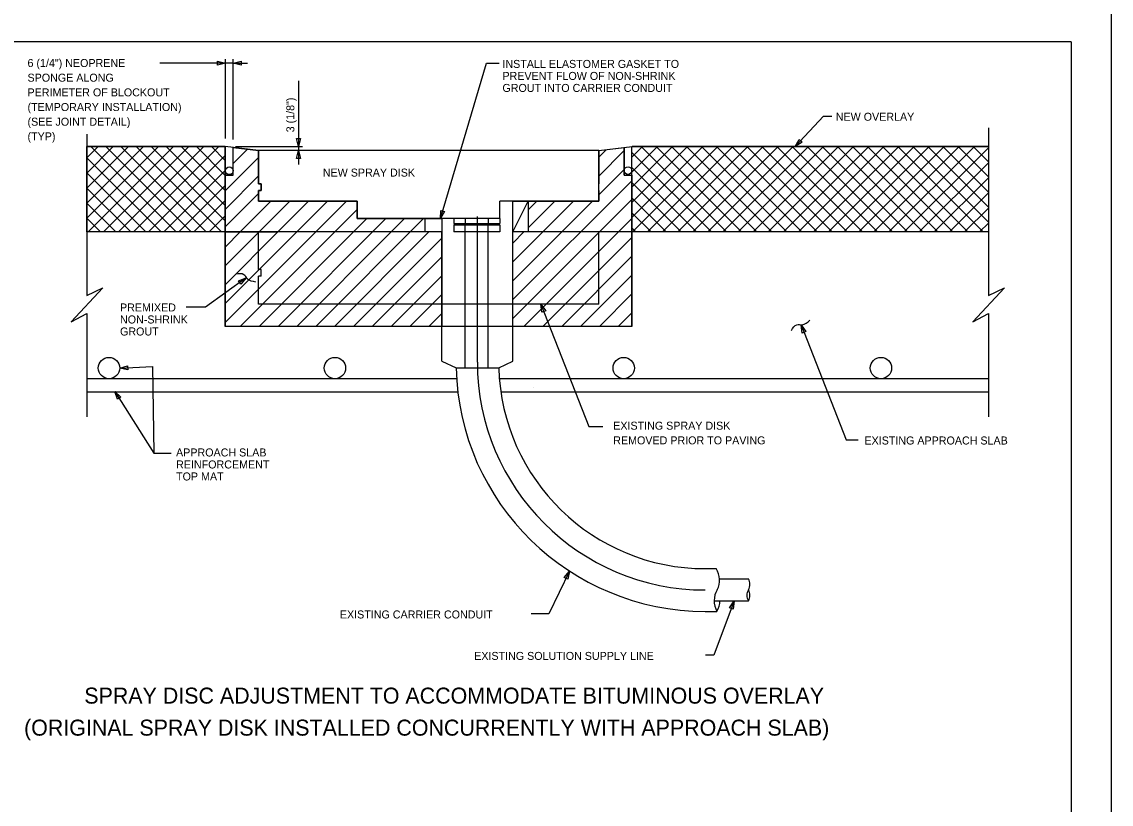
# Model space of a CAD drawing. Extents: x 3239 to 4230, y -4276 to -2494.
# Drawn here: x 3671.7 to 4080, y -3983 to -3689.8 of the extents above; entities that cross this region are included whole.
import ezdxf

# ---------------------------------------------------------------- set-up
doc = ezdxf.new("R2010")
doc.units = 0
doc.layers.add('2', color=7, linetype='Continuous')
doc.layers.add('PLT-BNDY', color=7, linetype='Continuous')

msp = doc.modelspace()

# ---------------------------------------------------------------- linework, layer by layer
at = {"layer": '2'}
for p, q in [((4065.03, -3697.29), (3279.03, -3697.29)), ((4065.03, -3697.29), (4065.03, -4261.29)), ((3751.06, -3705.33), (3723.37, -3705.33)), ((3748.04, -3733.57), (3748.04, -3703.83)), ((3750.91, -3733.93), (3750.91, -3703.83)), ((3750.91, -3705.33), (3756.26, -3705.33)), ((3775.35, -3711.98), (3775.35, -3743.26)), ((3696.08, -3731.87), (3696.08, -3792.42)), ((4033.98, -3729.58), (4033.98, -3792.42)), ((3747.94, -3736.57), (3696.08, -3736.57)), ((3696.08, -3740.81), (3700.32, -3736.57)), ((3696.08, -3746.47), (3705.98, -3736.57)), ((3696.08, -3752.13), (3711.63, -3736.57)), ((3696.08, -3757.79), (3717.29, -3736.57)), ((3696.08, -3763.44), (3722.95, -3736.57)), ((3696.6, -3768.57), (3728.6, -3736.57)), ((3697.53, -3736.57), (3729.53, -3768.57)), ((3702.26, -3768.57), (3734.26, -3736.57)), ((3703.18, -3736.57), (3735.18, -3768.57)), ((3707.92, -3768.57), (3739.92, -3736.57)), ((3708.84, -3736.57), (3740.84, -3768.57)), ((3713.57, -3768.57), (3745.57, -3736.57)), ((3714.5, -3736.57), (3746.5, -3768.57)), ((3719.23, -3768.57), (3747.94, -3739.86)), ((3720.15, -3736.57), (3747.94, -3764.36)), ((3725.81, -3736.57), (3747.94, -3758.7)), ((3731.47, -3736.57), (3747.94, -3753.05)), ((3737.12, -3736.57), (3747.94, -3747.39)), ((3742.78, -3736.57), (3747.94, -3741.73)), ((3760.44, -3738.07), (3747.94, -3736.57)), ((3747.94, -3768.57), (3747.94, -3736.57)), ((3747.94, -3738.07), (3747.94, -3768.57)), ((3750.91, -3747.29), (3750.91, -3736.93)), ((3750.91, -3742.95), (3756.28, -3737.57)), ((3751.73, -3736.57), (3776.85, -3736.57)), ((3760.44, -3750.57), (3760.44, -3738.07)), ((3760.44, -3750.57), (3760.44, -3738.07)), ((3887.94, -3738.07), (3760.44, -3738.07)), ((3887.94, -3738.07), (3900.44, -3736.57)), ((3887.94, -3740.55), (3890.76, -3737.73)), ((3887.94, -3757.07), (3887.94, -3738.07)), ((3887.94, -3738.07), (3887.94, -3750.57)), ((3887.94, -3747.6), (3897.47, -3738.07)), ((3897.47, -3747.29), (3897.47, -3736.93)), ((3900.34, -3768.57), (3900.34, -3736.57)), ((3900.34, -3740.52), (3904.28, -3736.57)), ((3900.34, -3746.17), (3909.94, -3736.57)), ((3900.34, -3751.83), (3915.6, -3736.57)), ((3900.34, -3757.49), (3921.25, -3736.57)), ((3900.34, -3763.14), (3926.91, -3736.57)), ((3900.34, -3738.74), (3930.18, -3768.57)), ((4033.98, -3736.57), (3900.44, -3736.57)), ((3900.57, -3768.57), (3932.57, -3736.57)), ((3903.83, -3736.57), (3935.83, -3768.57)), ((3906.22, -3768.57), (3938.22, -3736.57)), ((3909.49, -3736.57), (3941.49, -3768.57)), ((3911.88, -3768.57), (3943.88, -3736.57)), ((3915.15, -3736.57), (3947.15, -3768.57)), ((3917.54, -3768.57), (3949.54, -3736.57)), ((3920.8, -3736.57), (3952.8, -3768.57)), ((3923.2, -3768.57), (3955.2, -3736.57)), ((3926.46, -3736.57), (3958.46, -3768.57)), ((3928.85, -3768.57), (3960.85, -3736.57)), ((3932.12, -3736.57), (3964.12, -3768.57)), ((3934.51, -3768.57), (3966.51, -3736.57)), ((3937.77, -3736.57), (3969.77, -3768.57)), ((3940.17, -3768.57), (3972.17, -3736.57)), ((3943.43, -3736.57), (3975.43, -3768.57)), ((3945.82, -3768.57), (3977.82, -3736.57)), ((3949.09, -3736.57), (3981.09, -3768.57)), ((3951.48, -3768.57), (3983.48, -3736.57)), ((3954.75, -3736.57), (3986.75, -3768.57)), ((3957.14, -3768.57), (3989.14, -3736.57)), ((3960.4, -3736.57), (3992.4, -3768.57)), ((3962.79, -3768.57), (3994.79, -3736.57)), ((3966.06, -3736.57), (3998.06, -3768.57)), ((3968.45, -3768.57), (4000.45, -3736.57)), ((3971.72, -3736.57), (4003.72, -3768.57)), ((3974.11, -3768.57), (4006.11, -3736.57)), ((3977.37, -3736.57), (4009.37, -3768.57)), ((3979.76, -3768.57), (4011.76, -3736.57)), ((3983.03, -3736.57), (4015.03, -3768.57)), ((3985.42, -3768.57), (4017.42, -3736.57)), ((3988.69, -3736.57), (4020.69, -3768.57)), ((3991.08, -3768.57), (4023.08, -3736.57)), ((3994.34, -3736.57), (4026.34, -3768.57)), ((3996.73, -3768.57), (4028.73, -3736.57)), ((4000, -3736.57), (4032, -3768.57)), ((4002.39, -3768.57), (4033.98, -3736.98)), ((4005.66, -3736.57), (4033.98, -3764.9)), ((4011.31, -3736.57), (4033.98, -3759.24)), ((4016.97, -3736.57), (4033.98, -3753.59)), ((4022.63, -3736.57), (4033.98, -3747.93)), ((4028.28, -3736.57), (4033.98, -3742.27)), ((4033.94, -3736.57), (4033.98, -3736.62)), ((3696.08, -3740.78), (3723.87, -3768.57)), ((3747.94, -3753.18), (3760.44, -3740.68)), ((3900.34, -3744.39), (3924.52, -3768.57)), ((4008.05, -3768.57), (4033.98, -3742.64)), ((3696.08, -3746.44), (3718.21, -3768.57)), ((3724.89, -3768.57), (3747.94, -3745.52)), ((3750.91, -3747.29), (3748.04, -3747.29)), ((3748.04, -3759.96), (3760.44, -3747.56)), ((3887.94, -3754.69), (3897.47, -3745.16)), ((3897.47, -3747.29), (3900.34, -3747.29)), ((4013.71, -3768.57), (4033.98, -3748.29)), ((3696.08, -3752.1), (3712.56, -3768.57)), ((3730.55, -3768.57), (3747.94, -3751.18)), ((3761.44, -3750.57), (3760.44, -3750.57)), ((3761.44, -3750.57), (3760.44, -3750.57)), ((3761.44, -3753.07), (3761.44, -3750.57)), ((3761.44, -3753.07), (3761.44, -3750.57)), ((3855.76, -3793.92), (3900.34, -3749.34)), ((3900.34, -3750.05), (3918.86, -3768.57)), ((3747.94, -3766.65), (3760.44, -3754.15)), ((3761.44, -3753.07), (3760.44, -3753.07)), ((3760.44, -3757.07), (3760.44, -3753.07)), ((3760.44, -3757.07), (3760.44, -3753.07)), ((3760.44, -3753.07), (3761.44, -3753.07)), ((3887.94, -3753.07), (3887.94, -3757.07)), ((3888.2, -3768.57), (3900.34, -3756.44)), ((3900.34, -3755.71), (3913.21, -3768.57)), ((4019.36, -3768.57), (4033.98, -3753.95)), ((3696.08, -3757.75), (3706.9, -3768.57)), ((3736.2, -3768.57), (3747.94, -3756.83)), ((3747.94, -3781.29), (3772.16, -3757.07)), ((3747.94, -3795.39), (3786.26, -3757.07)), ((3753.57, -3768.57), (3765.07, -3757.07)), ((3753.57, -3803.94), (3797.34, -3760.18)), ((3797.34, -3757.07), (3760.44, -3757.07)), ((3767.71, -3768.57), (3779.21, -3757.07)), ((3781.85, -3768.57), (3793.35, -3757.07)), ((3797.34, -3763.57), (3797.34, -3757.07)), ((3887.94, -3757.07), (3850.84, -3757.07)), ((3850.84, -3763.57), (3850.84, -3757.07)), ((3855.76, -3779.78), (3878.47, -3757.07)), ((3861.5, -3766.99), (3871.42, -3757.07)), ((3861.5, -3760.3), (3864.73, -3757.07)), ((3874.06, -3768.57), (3885.56, -3757.07)), ((3900.34, -3758.74), (3900.34, -3768.57)), ((4025.02, -3768.57), (4033.98, -3759.61)), ((3696.08, -3763.41), (3701.24, -3768.57)), ((3741.86, -3768.57), (3747.94, -3762.49)), ((3767.72, -3803.94), (3808.09, -3763.57)), ((3781.86, -3803.94), (3822.23, -3763.57)), ((3796, -3768.57), (3801, -3763.57)), ((3850.84, -3763.57), (3797.34, -3763.57)), ((3850.84, -3763.57), (3797.34, -3763.57)), ((3821.08, -3763.57), (3797.44, -3763.57)), ((3810.14, -3768.57), (3815.14, -3763.57)), ((3833.6, -3763.57), (3833.6, -3765.34)), ((3837.81, -3763.57), (3837.81, -3765.34)), ((3842.44, -3817.31), (3842.44, -3762.79)), ((3846.49, -3763.57), (3846.49, -3765.34)), ((3850.84, -3763.57), (3850.84, -3765.34)), ((3859.88, -3803.94), (3900.34, -3763.49)), ((3900.34, -3761.36), (3907.55, -3768.57)), ((3747.94, -3768.57), (3696.08, -3768.57)), ((3747.52, -3768.57), (3747.94, -3768.15)), ((3747.94, -3768.57), (3767.71, -3768.57)), ((3747.94, -3803.94), (3747.94, -3768.57)), ((3829.11, -3768.57), (3747.94, -3768.57)), ((3748.04, -3774.1), (3753.57, -3768.57)), ((3748.04, -3788.24), (3767.71, -3768.57)), ((3748.04, -3802.39), (3781.85, -3768.57)), ((3760.44, -3782.57), (3760.44, -3768.57)), ((3760.62, -3803.94), (3796, -3768.57)), ((3774.77, -3803.94), (3810.14, -3768.57)), ((3788.91, -3803.94), (3824.28, -3768.57)), ((3829.11, -3816.98), (3829.11, -3768.57)), ((3833.6, -3765.34), (3850.84, -3765.34)), ((3833.6, -3765.84), (3850.84, -3765.84)), ((3833.6, -3765.84), (3833.6, -3768.57)), ((3850.84, -3768.57), (3833.6, -3768.57)), ((3837.81, -3819.48), (3837.81, -3765.84)), ((3846.49, -3819.48), (3846.49, -3765.84)), ((3850.84, -3765.84), (3850.84, -3768.57)), ((3855.76, -3816.98), (3855.76, -3768.57)), ((3855.76, -3772.73), (3859.92, -3768.57)), ((3855.76, -3786.87), (3874.06, -3768.57)), ((3855.76, -3801.01), (3888.2, -3768.57)), ((3900.34, -3768.57), (3855.76, -3768.57)), ((3887.94, -3795.57), (3887.94, -3768.57)), ((3900.34, -3767.02), (3901.89, -3768.57)), ((3900.34, -3803.94), (3900.34, -3768.57)), ((4033.98, -3768.57), (3900.44, -3768.57)), ((4030.68, -3768.57), (4033.98, -3765.26)), ((3796, -3803.94), (3829.11, -3770.83)), ((3866.97, -3803.94), (3900.34, -3770.58)), ((3803.05, -3803.94), (3829.11, -3777.88)), ((3874.07, -3803.94), (3900.34, -3777.67)), ((3761.44, -3782.57), (3760.44, -3782.57)), ((3760.44, -3795.57), (3760.44, -3785.07)), ((3761.44, -3785.07), (3760.44, -3785.07)), ((3761.44, -3785.07), (3761.44, -3782.57)), ((3810.14, -3803.94), (3829.11, -3784.97)), ((3881.12, -3803.94), (3900.34, -3784.72)), ((3702.11, -3789.51), (3690.21, -3802.3)), ((3696.08, -3792.42), (3702.11, -3789.51)), ((3817.19, -3803.94), (3829.11, -3792.02)), ((3888.21, -3803.94), (3900.34, -3791.81)), ((4040.02, -3789.51), (4028.12, -3802.3)), ((4033.98, -3792.42), (4040.02, -3789.51)), ((3887.94, -3795.57), (3760.44, -3795.57)), ((3690.21, -3802.3), (3696.08, -3799.17)), ((3696.08, -3799.17), (3696.08, -3837.88)), ((3824.24, -3803.94), (3829.11, -3799.07)), ((3895.26, -3803.94), (3900.34, -3798.86)), ((4028.12, -3802.3), (4033.98, -3799.17)), ((4033.98, -3799.17), (4033.98, -3837.88)), ((3900.34, -3803.94), (3747.94, -3803.94)), ((3829.11, -3816.98), (3834.44, -3819.48)), ((3850.44, -3819.48), (3855.76, -3816.98)), ((3834.47, -3819.48), (3850.47, -3819.48)), ((3834.65, -3823.61), (3696.08, -3823.61)), ((4033.98, -3823.61), (3850.7, -3823.61)), ((3955.76, -3823.61), (3857.61, -3823.61)), ((3835.13, -3828.61), (3696.08, -3828.61)), ((4033.98, -3828.61), (3851.27, -3828.61)), ((3927.88, -3894.75), (3931.98, -3894.75)), ((3876.96, -3895.65), (3869.19, -3911.74)), ((3933.22, -3898.51), (3944.02, -3898.51)), ((3931.21, -3906.83), (3944.02, -3906.83)), ((3869.19, -3911.74), (3862.57, -3911.74)), ((3927.88, -3910.75), (3932.23, -3910.75))]:
    msp.add_line(p, q, dxfattribs=at)
for points in [[(3745.04, -3704.58), (3748.04, -3705.33), (3745.04, -3706.08)], [(3753.91, -3706.08), (3750.91, -3705.33), (3753.91, -3704.58)], [(3776.1, -3733.57), (3775.35, -3736.57), (3774.6, -3733.57)], [(3964.14, -3734.89), (3961.55, -3736.57), (3963.05, -3733.86)], [(3696.08, -3736.57), (3747.94, -3736.57), (3747.94, -3768.57), (3696.08, -3768.57)], [(3750.91, -3736.93), (3760.44, -3738.07), (3760.44, -3750.57), (3761.44, -3750.57), (3761.44, -3753.07), (3760.44, -3753.07), (3760.44, -3757.07), (3797.34, -3757.07), (3797.34, -3763.57), (3829.11, -3763.57), (3829.11, -3768.57), (3829.11, -3768.57), (3829.11, -3803.94), (3748.04, -3803.94), (3748.04, -3747.29), (3750.91, -3747.29)], [(3774.6, -3741.07), (3775.35, -3738.07), (3776.1, -3741.07)], [(3897.47, -3736.93), (3897.47, -3747.29), (3900.34, -3747.29), (3900.34, -3803.94), (3855.76, -3803.94), (3855.76, -3770.32), (3855.76, -3768.57), (3861.5, -3757.07), (3887.94, -3757.07), (3887.94, -3738.07)], [(3900.34, -3736.57), (4033.98, -3736.57), (4033.98, -3768.57), (3900.34, -3768.57), (3900.34, -3747.29)], [(3830.16, -3760.91), (3828.58, -3763.57), (3828.72, -3760.48)], [(3855.76, -3757.07), (3861.5, -3757.07), (3861.5, -3768.57), (3855.76, -3768.57)], [(3822.94, -3763.57), (3829.11, -3763.57), (3829.11, -3768.57), (3822.94, -3768.57)], [(3752.96, -3786.89), (3755.84, -3785.75), (3753.83, -3788.11)], [(3866.67, -3798.64), (3866.27, -3795.57), (3868.06, -3798.09)], [(3964.17, -3806.46), (3963.77, -3803.4), (3965.56, -3805.91)], [(3711.4, -3820.18), (3708.37, -3819.59), (3711.32, -3818.69)], [(3707.52, -3831.26), (3706.55, -3828.33), (3708.79, -3830.46)], [(3874.98, -3898.03), (3876.96, -3895.65), (3876.33, -3898.68)], [(3936.93, -3909.38), (3938.68, -3906.83), (3938.34, -3909.9)]]:
    msp.add_lwpolyline(points, close=True, dxfattribs=at)
for points in [[(3828.58, -3763.57), (3845.89, -3705.24), (3850.67, -3705.24)], [(3961.55, -3736.57), (3972.19, -3725.13), (3975.29, -3725.13)], [(3755.84, -3785.75), (3740.51, -3796.73), (3733.26, -3796.73)], [(3866.27, -3795.57), (3884.28, -3841.53), (3889.5, -3841.53)], [(3963.77, -3803.4), (3980.68, -3846.45), (3985.15, -3846.45)], [(3708.37, -3819.59), (3720.62, -3818.94), (3721.17, -3851.46)], [(3706.55, -3828.33), (3721.17, -3851.46), (3721.17, -3851.46), (3727.65, -3851.46)], [(3938.68, -3906.83), (3931.09, -3927.23), (3927.99, -3927.23)]]:
    msp.add_lwpolyline(points, dxfattribs=at)
for centre, radius in [((3749.47, -3745.6), 1.43), ((3898.91, -3745.55), 1.43), ((3704.37, -3819.59), 4), ((3789.04, -3819.59), 4), ((3897.29, -3819.59), 4), ((3993.71, -3819.59), 4)]:
    msp.add_circle(centre, radius, dxfattribs=at)
for centre, radius, start, end in [((3927.88, -3817.31), 85.44, 180, 270), ((3927.88, -3817.31), 93.44, 181.336, 270), ((3927.88, -3817.31), 77.44, 181.6121, 270), ((3843.39, -3826.85), 20, 0, 2.777777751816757e-06), ((3925.31, -3899.03), 7.93, 332.7154, 32.7154), ((3940.42, -3900.59), 4.16, 330, 30), ((3939.29, -3906.82), 8.08, 149.1201, 209.1201), ((3947.62, -3904.75), 4.16, 150, 210), ((3940.42, -3904.75), 4.16, 330, 30), ((3925.3, -3906.6), 8.08, 329.1201, 358.4019)]:
    msp.add_arc(centre, radius, start, end, dxfattribs=at)
for points in [[(3752.01, -3784.22), (3754.91, -3784.46), (3756.15, -3786.01), (3759.32, -3787.22)], [(3960.18, -3805.44), (3962.17, -3803.31), (3964.16, -3803.31), (3967.08, -3801.59)]]:
    msp.add_spline(points, degree=3, dxfattribs=at)
at = {"layer": 'PLT-BNDY'}
msp.add_lwpolyline([(3239.03, -3682.29), (4080.03, -3682.29), (4080.03, -4276.29), (3239.03, -4276.29)], close=True, dxfattribs=at)

# ---------------------------------------------------------------- texts
at = {"layer": '2'}
for s, height, p in [('6 (1/4") NEOPRENE ', 3, (3673.83, -3706.74)), ('INSTALL ELASTOMER GASKET TO ', 3, (3851.84, -3707.08)), ('SPONGE ALONG ', 3, (3673.83, -3712.24)), ('PREVENT FLOW OF NON-SHRINK ', 3, (3851.84, -3711.58)), ('PERIMETER OF BLOCKOUT', 3, (3673.83, -3717.74)), ('GROUT INTO CARRIER CONDUIT', 3, (3851.84, -3716.08)), ('(TEMPORARY INSTALLATION)', 3, (3673.83, -3723.24)), ('NEW OVERLAY ', 3, (3976.78, -3726.88)), ('(SEE JOINT DETAIL) ', 3, (3673.83, -3728.74)), ('(TYP)', 3, (3673.83, -3734.24)), ('NEW SPRAY DISK', 3, (3784.51, -3747.81)), ('PREMIXED', 3, (3708.5, -3798.36)), ('NON-SHRINK', 3, (3708.5, -3802.86)), ('GROUT', 3, (3708.5, -3807.36)), ('EXISTING SPRAY DISK', 3, (3893.37, -3842.67)), ('REMOVED PRIOR TO PAVING', 3, (3893.37, -3848.17)), ('EXISTING APPROACH SLAB', 3, (3987.53, -3848.22)), ('APPROACH SLAB', 3, (3729.51, -3852.7)), ('REINFORCEMENT', 3, (3729.51, -3857.2)), ('TOP MAT', 3, (3729.51, -3861.7)), ('EXISTING CARRIER CONDUIT', 3, (3790.91, -3913.42)), ('EXISTING SOLUTION SUPPLY LINE', 3, (3841.25, -3928.96)), ('SPRAY DISC ADJUSTMENT TO ACCOMMODATE BITUMINOUS OVERLAY', 6, (3695.11, -3945.34)), ('(ORIGINAL SPRAY DISK INSTALLED CONCURRENTLY WITH APPROACH SLAB)', 6, (3672.53, -3957.34))]:
    msp.add_text(s, height=height, dxfattribs=at).set_placement(p)
msp.add_text('3 (1/8")', height=3, rotation=90, dxfattribs=at).set_placement((3773.85, -3731.22))

doc.saveas('drawing.dxf')
